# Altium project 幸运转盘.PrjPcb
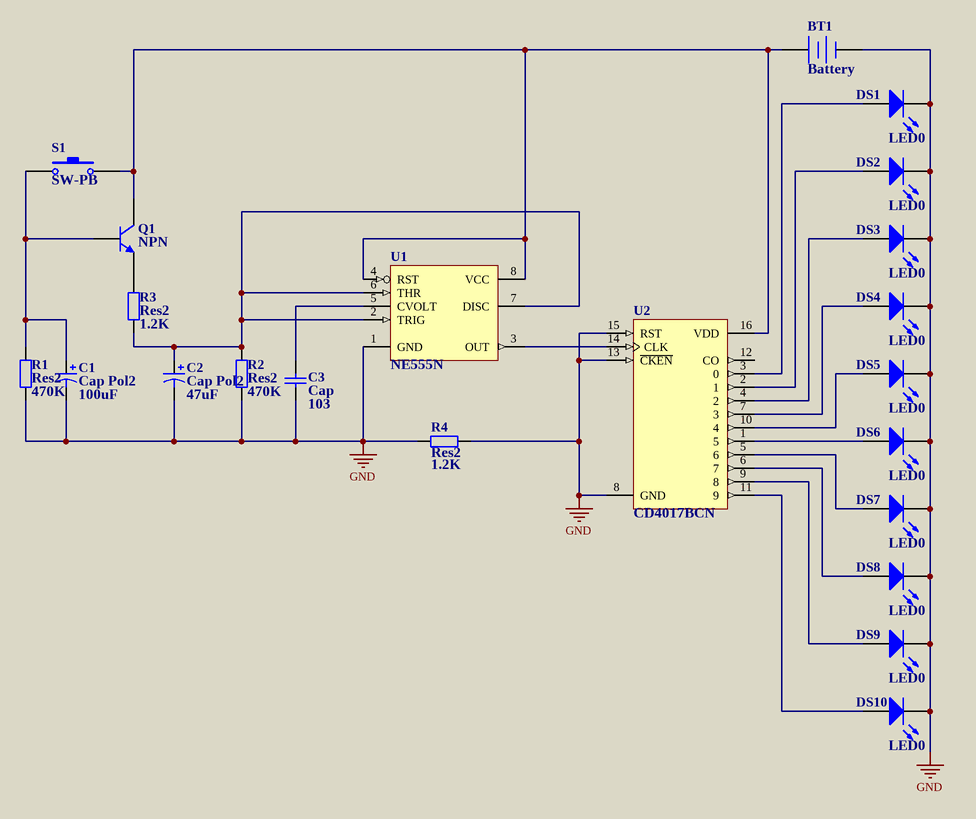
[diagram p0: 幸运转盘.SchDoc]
1 sheet, 22 parts. Net scope: global (net labels, ports and power ports of the same name join across sheets).
Board file: 幸运转盘.PcbDoc

## Sheet 幸运转盘.SchDoc
size A4

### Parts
BT1  Battery  [BAT-2]
C1  Cap Pol2  value 100uF  [电解电容-100uF]
C2  Cap Pol2  value 47uF  [电解电容-100uF]
C3  Cap  value 103  [CAPR2.54-5.1X3.2]
DS1  LED0  [发光二极管]
DS2  LED0  [发光二极管]
DS3  LED0  [发光二极管]
DS4  LED0  [发光二极管]
DS5  LED0  [发光二极管]
DS6  LED0  [发光二极管]
DS7  LED0  [发光二极管]
DS8  LED0  [发光二极管]
DS9  LED0  [发光二极管]
DS10  LED0  [发光二极管]
Q1  NPN  [TO-226-AA]
R1  Res2  value 470K  [AXIAL-0.4]
R2  Res2  value 470K  [AXIAL-0.4]
R3  Res2  value 1.2K  [AXIAL-0.4]
R4  Res2  value 1.2K  [AXIAL-0.4]
S1  SW-PB  [轻触开关]
U1  NE555N  [DIP8]
U2  CD4017BCN  [N16E]

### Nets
GND: BT1.2(-) C1.2 C2.2 C3.2 DS1.2(K) DS2.2(K) DS3.2(K) DS4.2(K) DS5.2(K) DS6.2(K) DS7.2(K) DS8.2(K) DS9.2(K) DS10.2(K) R1.1 R2.1 R4.1 R4.2 U1.1(GND) U2.8(GND) U2.13(~{CKEN}) U2.15(RST)
NetBT1_1: BT1.1(+) Q1.1(C) S1.2 U1.4(RST) U1.8(VCC) U2.16(VDD)
NetC1_1: C1.1 Q1.2(B) R1.2 S1.1
NetC2_1: C2.1 R2.2 R3.1 U1.2(TRIG) U1.6(THR) U1.7(DISC)
NetC3_1: C3.1 U1.5(CVOLT)
NetDS1_1: DS1.1(A) U2.3(0)
NetDS2_1: DS2.1(A) U2.2(1)
NetDS3_1: DS3.1(A) U2.4(2)
NetDS4_1: DS4.1(A) U2.7(3)
NetDS5_1: DS5.1(A) U2.10(4)
NetDS6_1: DS6.1(A) U2.1(5)
NetDS7_1: DS7.1(A) U2.5(6)
NetDS8_1: DS8.1(A) U2.6(7)
NetDS9_1: DS9.1(A) U2.9(8)
NetDS10_1: DS10.1(A) U2.11(9)
NetQ1_3: Q1.3(E) R3.2
NetU1_3: U1.3(OUT) U2.14(CLK)

Not connected (* = marked no-connect by the designer): U2 12(CO)

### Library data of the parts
BT1 = Battery: Multicell Battery; value: 3V
C1 C2 = Cap Pol2: Polarized Capacitor (Axial)
C3 = Cap: Capacitor
DS1-DS10 = LED0: Typical INFRARED GaAs LED
Q1 = NPN: NPN Bipolar Transistor
R1-R4 = Res2: Resistor
S1 = SW-PB: Switch
U1 = NE555N: General-Purpose Single Bipolar Timer; Code - JEDEC: MO-001-AN
U2 = CD4017BCN: Decade Counter/Divider with 10 Decoded Outputs; Package Information: Latest Revision: 2000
